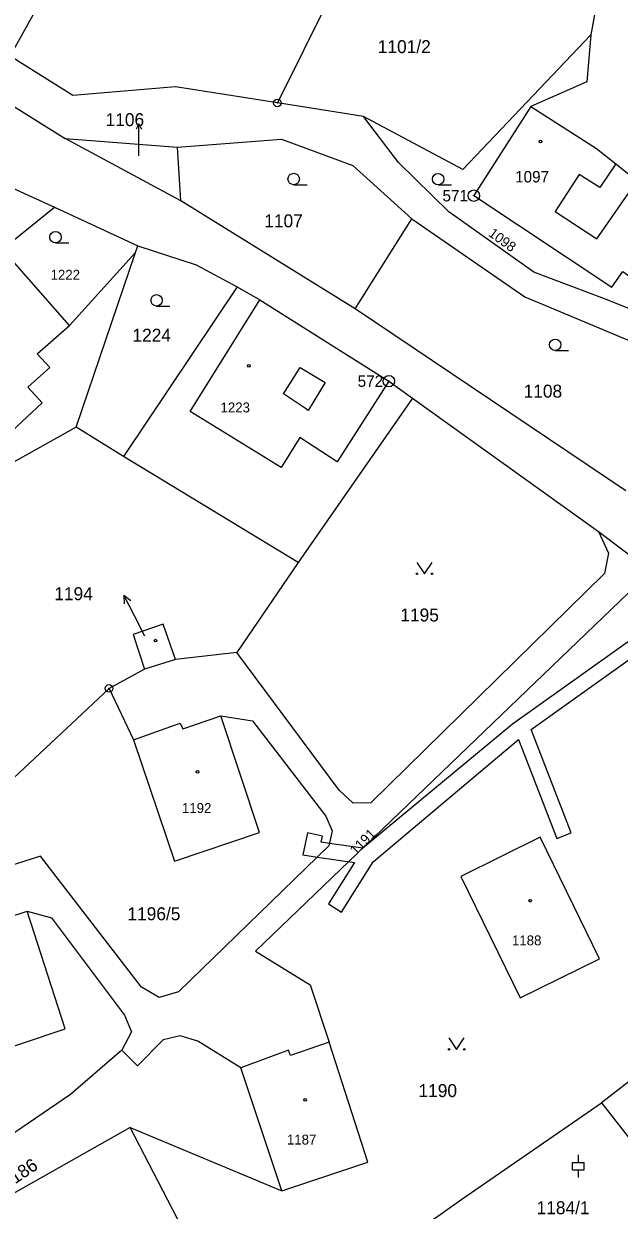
# Model space of a CAD drawing. Extents: x -504988 to -494607, y -1123820 to -1114018.
# Drawn here: x -497790.5 to -497712.4, y -1119487.8 to -1119332.3 of the extents above; entities that cross this region are included whole.
import ezdxf

# ---------------------------------------------------------------- set-up
doc = ezdxf.new("R2010")
doc.units = 0
for name, color, linetype in [('Hranice parcel', 7, 'Continuous'), ('Parcelní čísla', 7, 'Continuous'), ('Pop  PČ popisy', 7, 'Continuous'), ('Vnitřní kresba', 7, 'Continuous'), ('Věcná břemena k části', 7, 'Continuous'), ('Značky bodu BP', 7, 'Continuous'), ('Značky budov', 7, 'Continuous'), ('Značky kultur', 7, 'Continuous')]:
    doc.layers.add(name, color=color, linetype=linetype)

msp = doc.modelspace()

# ---------------------------------------------------------------- linework, layer by layer
at = {"layer": 'Hranice parcel'}
for p, q in [((-497792.3, -1119336.49), (-497770.13, -1119296.59)), ((-497739.35, -1119306.76), (-497757.24, -1119342.64)), ((-497745.92, -1119344.42), (-497757.24, -1119342.64)), ((-497785.08, -1119347.29), (-497770.34, -1119348.44)), ((-497769.9, -1119355.47), (-497785.08, -1119347.29)), ((-497769.9, -1119355.47), (-497770.34, -1119348.44)), ((-497791.93, -1119353.79), (-497786.48, -1119356.31)), ((-497747.03, -1119369.61), (-497769.9, -1119355.47)), ((-497793.28, -1119361.8), (-497786.48, -1119356.31)), ((-497786.48, -1119356.31), (-497775.55, -1119361.37)), ((-497747.03, -1119369.61), (-497739.62, -1119357.84)), ((-497775.87, -1119362.26), (-497775.55, -1119361.37)), ((-497784.52, -1119371.82), (-497793.28, -1119361.8)), ((-497775.87, -1119362.26), (-497784.52, -1119371.82)), ((-497783.64, -1119385.14), (-497775.87, -1119362.26)), ((-497762.52, -1119366.74), (-497777.43, -1119388.98)), ((-497711.51, -1119393.46), (-497747.03, -1119369.61)), ((-497739.51, -1119381.32), (-497754.5, -1119402.88)), ((-497739.51, -1119381.32), (-497715.1, -1119398.79)), ((-497783.64, -1119385.14), (-497805.4, -1119397.27)), ((-497777.43, -1119388.98), (-497783.64, -1119385.14)), ((-497754.5, -1119402.88), (-497777.43, -1119388.98)), ((-497715.1, -1119398.79), (-497705.77, -1119405.86)), ((-497754.5, -1119402.88), (-497762.56, -1119414.65)), ((-497770.6, -1119415.58), (-497774.66, -1119416.85)), ((-497762.56, -1119414.65), (-497770.6, -1119415.58)), ((-497774.66, -1119416.85), (-497779.32, -1119419.38)), ((-497818.6, -1119456.12), (-497779.32, -1119419.38)), ((-497779.32, -1119419.38), (-497776.09, -1119426.13)), ((-497756.65, -1119485.23), (-497762.04, -1119469.11)), ((-497714.71, -1119473.71), (-497700, -1119492.59)), ((-497776.55, -1119476.94), (-497808.66, -1119495.02)), ((-497761.28, -1119506.28), (-497776.55, -1119476.94)), ((-497776.55, -1119476.94), (-497756.65, -1119485.23))]:
    msp.add_line(p, q, dxfattribs=at)
for points in [[(-497864.11, -1119240.17), (-497860.41, -1119251.27), (-497855.42, -1119260.18), (-497846.83, -1119269.46), (-497832.13, -1119284.19), (-497821.03, -1119311.77), (-497813.65, -1119322.79), (-497808.26, -1119330.12), (-497799.03, -1119338.6), (-497785.08, -1119347.29)], [(-497730.68, -1119289.37), (-497718.64, -1119300.53), (-497714.03, -1119309.16), (-497714.28, -1119323.63), (-497716.11, -1119333.69)], [(-497716.11, -1119333.69), (-497732.93, -1119351.38), (-497745.92, -1119344.42)], [(-497716.11, -1119333.69), (-497716.63, -1119339.87), (-497724.01, -1119343.12)], [(-497757.24, -1119342.64), (-497770.58, -1119340.54), (-497784.06, -1119341.66), (-497792.3, -1119336.49)], [(-497698.2, -1119376.95), (-497706.35, -1119371.52), (-497714.32, -1119368.3), (-497723.58, -1119364.8), (-497734.74, -1119356.89), (-497741.36, -1119350.44), (-497745.92, -1119344.42)], [(-497724.01, -1119343.12), (-497731.48, -1119354.79), (-497713.36, -1119366.8), (-497711.92, -1119364.75), (-497709.96, -1119366.12), (-497705.69, -1119360), (-497707.63, -1119358.64), (-497705.88, -1119356.15)], [(-497724.01, -1119343.12), (-497715.38, -1119348.62), (-497712.86, -1119350.62), (-497710.05, -1119352.84), (-497705.88, -1119356.15)], [(-497770.34, -1119348.44), (-497756.7, -1119347.4), (-497747.35, -1119350.82), (-497739.62, -1119357.84)], [(-497739.62, -1119357.84), (-497724.77, -1119368.05), (-497705.37, -1119376.17), (-497700.66, -1119380.56)], [(-497775.55, -1119361.37), (-497767.88, -1119363.84), (-497762.52, -1119366.74)], [(-497762.52, -1119366.74), (-497759.52, -1119368.43), (-497742.61, -1119379.1), (-497739.51, -1119381.32)], [(-497810.08, -1119368.74), (-497804.31, -1119376.78), (-497795.43, -1119388.74), (-497788.1, -1119381.95), (-497789.99, -1119379.91), (-497787.08, -1119377.31), (-497788.73, -1119375.5), (-497784.52, -1119371.82)], [(-497715.1, -1119398.79), (-497713.81, -1119401.66), (-497714.35, -1119404.33), (-497744.99, -1119434.37), (-497747.3, -1119434.43), (-497749.12, -1119432.72), (-497762.56, -1119414.65)], [(-497705.77, -1119405.86), (-497708.27, -1119405.63), (-497711.19, -1119406.83), (-497760.1, -1119453.82), (-497752.95, -1119458.24), (-497750.43, -1119465.73)], [(-497770.6, -1119415.58), (-497772.2, -1119410.94), (-497776.17, -1119412.31), (-497774.66, -1119416.85)], [(-497764.64, -1119422.96), (-497760.49, -1119423.62), (-497750.89, -1119436.12), (-497750.03, -1119438.04), (-497750.49, -1119440.01), (-497770.2, -1119459.15), (-497772.76, -1119459.9), (-497775.04, -1119458.54), (-497788.3, -1119441.34), (-497803.51, -1119446.21), (-497801.66, -1119451.79)], [(-497776.09, -1119426.13), (-497769.97, -1119423.93), (-497769.65, -1119424.65), (-497764.64, -1119422.96)], [(-497776.09, -1119426.13), (-497770.75, -1119442.03), (-497759.58, -1119438.25), (-497764.64, -1119422.96)], [(-497725.37, -1119459.93), (-497714.98, -1119454.8), (-497722.77, -1119438.87), (-497733.18, -1119444.01), (-497725.37, -1119459.93)], [(-497801.66, -1119451.79), (-497795.42, -1119449.46), (-497795.17, -1119450.22), (-497790.08, -1119448.55)], [(-497801.66, -1119451.79), (-497796.46, -1119467.81), (-497785.06, -1119464), (-497790.08, -1119448.55)], [(-497790.08, -1119448.55), (-497786.88, -1119449.43), (-497777.28, -1119462.22), (-497776.39, -1119464.37), (-497777.62, -1119466.8)], [(-497698.21, -1119460.22), (-497709.69, -1119469.8), (-497714.71, -1119473.71)], [(-497762.04, -1119469.11), (-497767.68, -1119465.6), (-497769.99, -1119464.92), (-497772.24, -1119465.44), (-497775.58, -1119468.85), (-497777.62, -1119466.8)], [(-497750.43, -1119465.73), (-497755.53, -1119467.47), (-497755.8, -1119466.78), (-497762.04, -1119469.11)], [(-497756.65, -1119485.23), (-497745.38, -1119481.47), (-497750.43, -1119465.73)], [(-497777.62, -1119466.8), (-497784.36, -1119472.61), (-497793.46, -1119478.81)], [(-497761.28, -1119506.28), (-497733.05, -1119486.3), (-497714.71, -1119473.71)]]:
    msp.add_lwpolyline(points, dxfattribs=at)
at = {"layer": 'Pop  PČ popisy'}
for p, q in [((-497775.4, -1119345.37), (-497775.75, -1119346.07)), ((-497775.4, -1119347.47), (-497775.4, -1119345.37)), ((-497775.4, -1119345.37), (-497775.05, -1119346.07)), ((-497775.4, -1119349.57), (-497775.4, -1119347.47)), ((-497776, -1119409.84), (-497777.36, -1119407.17)), ((-497777.36, -1119407.17), (-497776.46, -1119407.83)), ((-497777.36, -1119407.17), (-497777.35, -1119408.29)), ((-497774.64, -1119412.52), (-497776, -1119409.84))]:
    msp.add_line(p, q, dxfattribs=at)
at = {"layer": 'Vnitřní kresba'}
for p, q in [((-497712.86, -1119350.62), (-497714.95, -1119353.72)), ((-497717.65, -1119352), (-497720.82, -1119356.87)), ((-497714.95, -1119353.72), (-497717.65, -1119352)), ((-497715.34, -1119360.43), (-497710.05, -1119352.84)), ((-497720.82, -1119356.87), (-497715.34, -1119360.43)), ((-497768.66, -1119383.08), (-497759.52, -1119368.43)), ((-497756.44, -1119380.76), (-497754.23, -1119377.3)), ((-497754.23, -1119377.3), (-497750.96, -1119379.28)), ((-497750.96, -1119379.28), (-497753.18, -1119382.96)), ((-497742.61, -1119379.1), (-497749.39, -1119389.66)), ((-497753.57, -1119382.7), (-497756.44, -1119380.76)), ((-497756.74, -1119390.44), (-497768.66, -1119383.08)), ((-497753.18, -1119382.96), (-497753.57, -1119382.7)), ((-497754.3, -1119386.5), (-497756.74, -1119390.44)), ((-497749.39, -1119389.66), (-497754.3, -1119386.5))]:
    msp.add_line(p, q, dxfattribs=at)
at = {"layer": 'Věcná břemena k části'}
msp.add_lwpolyline([(-497753.92, -1119441.18), (-497751.99, -1119441.47), (-497747.11, -1119442.19), (-497750.53, -1119447.61), (-497748.84, -1119448.68), (-497744.68, -1119442.09), (-497725.6, -1119426.06), (-497720.57, -1119439.03), (-497718.71, -1119438.3), (-497723.96, -1119424.76), (-497704.53, -1119410.93), (-497703.95, -1119411.75), (-497702.32, -1119410.59), (-497702.9, -1119409.77), (-497701.85, -1119409.02), (-497703.46, -1119407.72), (-497726.38, -1119424.04), (-497746.05, -1119440.32), (-497750.41, -1119439.68), (-497751.5, -1119439.52), (-497751.33, -1119438.73), (-497753.28, -1119438.3)], close=True, dxfattribs=at)
at = {"layer": 'Značky bodu BP'}
for centre, radius in [((-497757.24, -1119342.64), 0.5), ((-497757.24, -1119342.64), 0.0303), ((-497731.48, -1119354.79), 0.75), ((-497731.48, -1119354.79), 0.03), ((-497742.61, -1119379.1), 0.75), ((-497742.61, -1119379.1), 0.03), ((-497779.32, -1119419.38), 0.5), ((-497779.32, -1119419.38), 0.0303)]:
    msp.add_circle(centre, radius, dxfattribs=at)
at = {"layer": 'Značky budov'}
for centre in [(-497722.73, -1119347.68), (-497760.99, -1119377.1), (-497773.22, -1119413.11), (-497767.72, -1119430.3), (-497724.08, -1119447.2), (-497753.61, -1119473.31)]:
    msp.add_circle(centre, 0.175, dxfattribs=at)
at = {"layer": 'Značky kultur'}
for p, q in [((-497755.1, -1119353.36), (-497753.35, -1119353.36)), ((-497736.16, -1119353.38), (-497734.41, -1119353.38)), ((-497786.35, -1119360.98), (-497784.6, -1119360.98)), ((-497773.08, -1119369.26), (-497771.33, -1119369.26)), ((-497720.79, -1119375.08), (-497719.04, -1119375.08)), ((-497718.51, -1119481.49), (-497717.01, -1119481.49)), ((-497718.51, -1119482.49), (-497718.51, -1119481.49)), ((-497717.76, -1119481.49), (-497717.76, -1119480.49)), ((-497717.01, -1119482.49), (-497717.01, -1119481.49)), ((-497718.51, -1119482.49), (-497717.01, -1119482.49)), ((-497717.76, -1119483.49), (-497717.76, -1119482.49))]:
    msp.add_line(p, q, dxfattribs=at)
for points in [[(-497738.94, -1119402.85), (-497737.94, -1119404.35), (-497736.94, -1119402.85)], [(-497734.73, -1119465.18), (-497733.73, -1119466.68), (-497732.73, -1119465.18)]]:
    msp.add_lwpolyline(points, dxfattribs=at)
for centre, radius in [((-497755.1, -1119352.61), 0.75), ((-497736.16, -1119352.63), 0.75), ((-497786.35, -1119360.23), 0.75), ((-497773.08, -1119368.51), 0.75), ((-497720.79, -1119374.33), 0.75), ((-497738.94, -1119404.35), 0.1), ((-497736.94, -1119404.35), 0.1), ((-497734.73, -1119466.68), 0.1), ((-497732.73, -1119466.68), 0.1)]:
    msp.add_circle(centre, radius, dxfattribs=at)

# ---------------------------------------------------------------- texts
at = {"layer": 'Parcelní čísla'}
for s, height, p in [('1101/2', 1.7, (-497744.07, -1119336.11)), ('1106', 1.7, (-497779.77, -1119345.68)), ('1097', 1.5, (-497726.06, -1119353.06)), ('1107', 1.7, (-497758.96, -1119358.94)), ('1222', 1.3, (-497786.99, -1119365.81)), ('1224', 1.7, (-497776.25, -1119373.93)), ('1108', 1.7, (-497724.94, -1119381.26)), ('1223', 1.3, (-497764.7, -1119383.2)), ('1194', 1.7, (-497786.5, -1119407.81)), ('1195', 1.7, (-497741.11, -1119410.6)), ('1192', 1.3, (-497769.76, -1119435.7)), ('1196/5', 1.7, (-497776.91, -1119449.76)), ('1188', 1.3, (-497726.47, -1119453.05)), ('1190', 1.7, (-497738.73, -1119472.94)), ('1187', 1.3, (-497755.99, -1119479.16)), ('1184/1', 1.7, (-497723.24, -1119488.29))]:
    msp.add_text(s, height=height, dxfattribs=at).set_placement(p)
for s, height, rotation, p in [('1098', 1.3, 324, (-497729.66, -1119359.97)), ('1191', 1.3, 45, (-497746.96, -1119441.3)), ('1186', 1.7, 34, (-497792.69, -1119485.09))]:
    msp.add_text(s, height=height, rotation=rotation, dxfattribs=at).set_placement(p)
at = {"layer": 'Značky bodu BP'}
for s, p in [('571', (-497735.58, -1119355.54)), ('572', (-497746.71, -1119379.85))]:
    msp.add_text(s, height=1.5, dxfattribs=at).set_placement(p)

doc.saveas('drawing.dxf')
